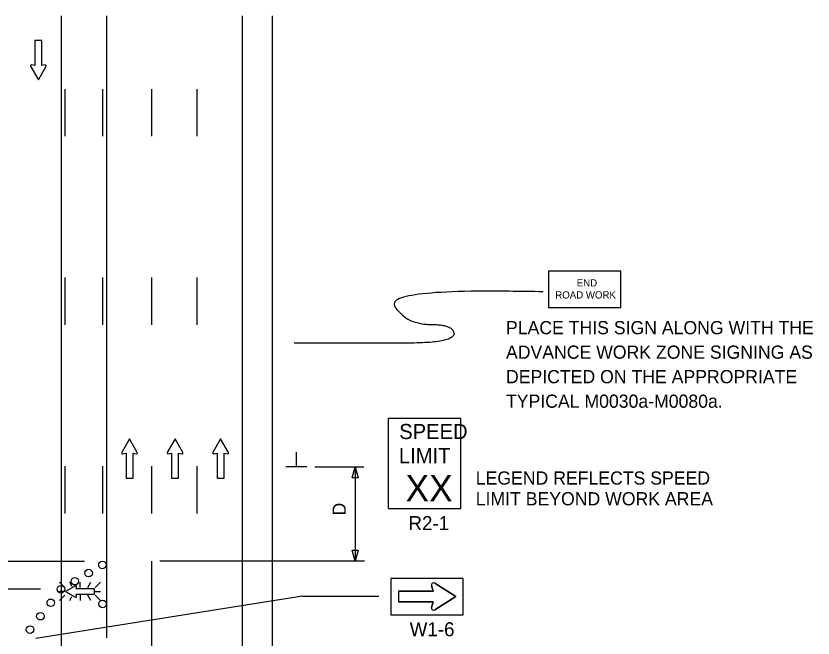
# Model space of a CAD drawing. Extents: x 16544 to 19504, y 5662 to 6909.
# Drawn here: x 16987.5 to 17410.3, y 6550.1 to 6880 of the extents above; entities that cross this region are included whole.
import ezdxf

# ---------------------------------------------------------------- set-up
doc = ezdxf.new("R2010")
doc.units = 0
for name, color, linetype in [('ALI_LEGAL_EX', 7, 'Continuous'), ('MT_SCRATCH_LEVEL_E', 7, 'Continuous'), ('PAVT_EDGE_EX', 7, 'Continuous'), ('TRAFFIC_SIGNS_PR', 7, 'Continuous'), ('TYPICAL_TEXT_DIMEN_PR', 7, 'Continuous')]:
    doc.layers.add(name, color=color, linetype=linetype)

msp = doc.modelspace()

# ---------------------------------------------------------------- linework, layer by layer
at = {"layer": 'ALI_LEGAL_EX'}
for points in [[(17013.46, 6841.23), (17013.46, 6816.23)], [(17033.46, 6841.23), (17033.46, 6816.23)], [(17059.46, 6841.23), (17059.46, 6816.23)], [(17083.46, 6841.23), (17083.46, 6816.23)], [(17013.46, 6741.23), (17013.46, 6716.23)], [(17013.46, 6741.23), (17013.46, 6716.23)], [(17033.46, 6741.23), (17033.46, 6716.23)], [(17033.46, 6741.23), (17033.46, 6716.23)], [(17059.46, 6741.23), (17059.46, 6716.23)], [(17059.46, 6741.23), (17059.46, 6716.23)], [(17083.46, 6741.23), (17083.46, 6716.23)], [(17013.46, 6641.23), (17013.46, 6616.23)], [(17013.46, 6641.23), (17013.46, 6616.23)], [(17033.46, 6641.23), (17033.46, 6616.23)], [(17033.46, 6641.23), (17033.46, 6616.23)], [(17059.46, 6641.23), (17059.46, 6616.23)], [(17059.46, 6641.23), (17059.46, 6616.23)], [(17083.46, 6641.23), (17083.46, 6616.23)]]:
    msp.add_lwpolyline(points, dxfattribs=at)
at = {"layer": 'MT_SCRATCH_LEVEL_E'}
for p, q in [((17001.2, 6866.95), (16997.46, 6866.95)), ((16997.46, 6866.95), (16997.46, 6853.69)), ((17001.2, 6866.95), (16997.46, 6866.95)), ((16997.46, 6866.95), (16997.46, 6853.69)), ((17001.2, 6853.69), (17001.2, 6866.95)), ((17001.2, 6853.69), (17001.2, 6866.95)), ((16995.2, 6853.32), (16999.35, 6846.09)), ((16995.2, 6853.32), (16999.35, 6846.09)), ((16997.46, 6853.69), (16995.68, 6854.01)), ((16997.46, 6853.69), (16995.68, 6854.01)), ((16999.35, 6846.09), (17003.46, 6853.32)), ((16999.35, 6846.09), (17003.46, 6853.32)), ((17002.98, 6854.01), (17001.2, 6853.69)), ((17002.98, 6854.01), (17001.2, 6853.69)), ((17047.7, 6655.73), (17043.59, 6648.49)), ((17047.7, 6655.73), (17043.59, 6648.49)), ((17051.85, 6648.49), (17047.7, 6655.73)), ((17051.85, 6648.49), (17047.7, 6655.73)), ((17071.87, 6655.73), (17067.76, 6648.49)), ((17071.87, 6655.73), (17067.76, 6648.49)), ((17076.02, 6648.49), (17071.87, 6655.73)), ((17076.02, 6648.49), (17071.87, 6655.73)), ((17096.04, 6655.73), (17091.93, 6648.49)), ((17096.04, 6655.73), (17091.93, 6648.49)), ((17100.19, 6648.49), (17096.04, 6655.73)), ((17100.19, 6648.49), (17096.04, 6655.73)), ((17044.07, 6647.81), (17045.85, 6648.12)), ((17044.07, 6647.81), (17045.85, 6648.12)), ((17045.85, 6648.12), (17045.85, 6634.86)), ((17045.85, 6648.12), (17045.85, 6634.86)), ((17049.59, 6634.86), (17049.59, 6648.12)), ((17049.59, 6648.12), (17051.37, 6647.81)), ((17049.59, 6634.86), (17049.59, 6648.12)), ((17049.59, 6648.12), (17051.37, 6647.81)), ((17068.24, 6647.81), (17070.02, 6648.12)), ((17068.24, 6647.81), (17070.02, 6648.12)), ((17070.02, 6648.12), (17070.02, 6634.86)), ((17070.02, 6648.12), (17070.02, 6634.86)), ((17073.76, 6634.86), (17073.76, 6648.12)), ((17073.76, 6648.12), (17075.54, 6647.81)), ((17073.76, 6634.86), (17073.76, 6648.12)), ((17073.76, 6648.12), (17075.54, 6647.81)), ((17092.41, 6647.81), (17094.19, 6648.12)), ((17092.41, 6647.81), (17094.19, 6648.12)), ((17094.19, 6648.12), (17094.19, 6634.86)), ((17094.19, 6648.12), (17094.19, 6634.86)), ((17097.93, 6634.86), (17097.93, 6648.12)), ((17097.93, 6648.12), (17099.71, 6647.81)), ((17097.93, 6634.86), (17097.93, 6648.12)), ((17097.93, 6648.12), (17099.71, 6647.81)), ((17045.85, 6634.86), (17049.59, 6634.86)), ((17045.85, 6634.86), (17049.59, 6634.86)), ((17070.02, 6634.86), (17073.76, 6634.86)), ((17070.02, 6634.86), (17073.76, 6634.86)), ((17094.19, 6634.86), (17097.93, 6634.86)), ((17094.19, 6634.86), (17097.93, 6634.86))]:
    msp.add_line(p, q, dxfattribs=at)
for centre, start, end in [((16995.61, 6853.55), 80.0362, 209.7731), ((16995.61, 6853.55), 80.0362, 209.7731), ((17003.05, 6853.55), 330.4248, 99.9638), ((17003.05, 6853.55), 330.4248, 99.9638), ((17044, 6648.26), 150.4248, 279.9638), ((17044, 6648.26), 150.4248, 279.9638), ((17051.44, 6648.27), 260.0362, 29.7731), ((17051.44, 6648.27), 260.0362, 29.7731), ((17068.17, 6648.26), 150.4248, 279.9638), ((17068.17, 6648.26), 150.4248, 279.9638), ((17075.61, 6648.27), 260.0362, 29.7731), ((17075.61, 6648.27), 260.0362, 29.7731), ((17092.34, 6648.26), 150.4248, 279.9638), ((17092.34, 6648.26), 150.4248, 279.9638), ((17099.78, 6648.27), 260.0362, 29.7731), ((17099.78, 6648.27), 260.0362, 29.7731)]:
    msp.add_arc(centre, 0.463, start, end, dxfattribs=at)
at = {"layer": 'PAVT_EDGE_EX'}
for p, q in [((17011.46, 6880.02), (17011.46, 6516.57)), ((17035.46, 6880.02), (17035.46, 6550.27)), ((17107.46, 6880.02), (17107.46, 6106.05)), ((17123.46, 6880.02), (17123.46, 6106.05)), ((17011.46, 6794.72), (17011.46, 6522.22)), ((17035.46, 6794.72), (17035.46, 6552.57)), ((17059.46, 6590.85), (17059.46, 6538.35))]:
    msp.add_line(p, q, dxfattribs=at)
at = {"layer": 'TRAFFIC_SIGNS_PR'}
for p, q in [((17185.03, 6666.76), (17223.43, 6666.76)), ((17185.03, 6618.76), (17185.03, 6666.76)), ((17223.43, 6618.76), (17223.43, 6666.76)), ((17185.03, 6618.76), (17223.43, 6618.76)), ((17010.54, 6579.66), (17013.36, 6576.84)), ((17017.26, 6577.48), (17016, 6579.66)), ((17021.45, 6576.84), (17021.45, 6579.66)), ((17025.58, 6576.84), (17027.21, 6579.66)), ((17029.53, 6576.84), (17032.35, 6579.66)), ((17208.8, 6574.87), (17207.96, 6577.93)), ((17209.64, 6579.18), (17220.8, 6572.07)), ((17013.36, 6574.81), (17010.54, 6574.81)), ((17010.54, 6569.96), (17013.36, 6572.78)), ((17015.98, 6569.96), (17017.19, 6572.05)), ((17021.45, 6572.78), (17021.45, 6569.96)), ((17027.24, 6569.96), (17025.61, 6572.78)), ((17029.53, 6574.81), (17032.35, 6574.81)), ((17029.53, 6572.78), (17032.35, 6569.96)), ((17190.4, 6574.87), (17208.8, 6574.87)), ((17190.4, 6574.87), (17190.4, 6569.27)), ((17220.8, 6572.07), (17209.64, 6564.97)), ((17208.8, 6569.27), (17190.4, 6569.27)), ((17207.96, 6566.21), (17208.8, 6569.27))]:
    msp.add_line(p, q, dxfattribs=at)
for points in [[(17269.97, 6725.41), (17308.37, 6725.41), (17308.37, 6744.61), (17269.97, 6744.61)], [(17186.4, 6562.47), (17224.8, 6562.47), (17224.8, 6581.67), (17186.4, 6581.67)]]:
    msp.add_lwpolyline(points, close=True, dxfattribs=at)
for points in [[(17019.12, 6577.82), (17013.81, 6574.81), (17019.12, 6571.77)], [(17019.62, 6572.13), (17019.39, 6573.42), (17029.11, 6573.42), (17029.11, 6576.17), (17019.39, 6576.17), (17019.62, 6577.47)], [(17207.96, 6577.93), (17208.8, 6574.87), (17190.4, 6574.87), (17190.4, 6569.27), (17208.8, 6569.27), (17207.96, 6566.21)], [(17209.64, 6564.97), (17220.8, 6572.07), (17209.64, 6579.18)]]:
    msp.add_lwpolyline(points, dxfattribs=at)
for centre in [(17033.35, 6588.85), (17033.35, 6588.85), (17026.02, 6584.54), (17018.69, 6580.23), (17011.36, 6575.93), (17005.94, 6568.79), (17033.4, 6568.18), (17000.45, 6561.67), (16994.95, 6554.54)]:
    msp.add_circle(centre, 2, dxfattribs=at)
for centre, radius, start, end in [((17019.28, 6577.53), 0.341, 350.7308, 118.8916), ((17209.04, 6578.23), 1.12, 57.5304, 195.3269), ((17209.04, 6578.23), 1.12, 57.5304, 195.3269), ((17019.28, 6572.07), 0.341, 241.4833, 9.9593), ((17209.04, 6565.92), 1.12, 164.6731, 302.4696), ((17209.04, 6565.92), 1.12, 164.6731, 302.4696)]:
    msp.add_arc(centre, radius, start, end, dxfattribs=at)
at = {"layer": 'TYPICAL_TEXT_DIMEN_PR'}
for p, q in [((17136.22, 6640.85), (17136.22, 6648.64)), ((17141.84, 6640.85), (17130.59, 6640.85)), ((17146.09, 6640.85), (17172.09, 6640.85)), ((17165.89, 6634.99), (17167.46, 6640.85)), ((17167.46, 6640.85), (17167.46, 6590.85)), ((17167.46, 6640.85), (17169.03, 6634.99)), ((17167.46, 6634.99), (17165.89, 6634.99)), ((17169.03, 6634.99), (17167.46, 6634.99)), ((17167.46, 6590.85), (17165.89, 6596.72)), ((17165.89, 6596.72), (17167.46, 6596.72)), ((17167.46, 6596.72), (17169.03, 6596.72)), ((17169.03, 6596.72), (17167.46, 6590.85)), ((16874.36, 6590.85), (17023.87, 6590.85)), ((17172.46, 6590.85), (17063.88, 6590.85)), ((17000.44, 6575.93), (16848.78, 6575.93)), ((17139.51, 6572.32), (16997.97, 6549.9)), ((17139.51, 6572.32), (17179.97, 6572.32))]:
    msp.add_line(p, q, dxfattribs=at)
msp.add_open_spline([(17267.18, 6733.73), (17182.47, 6735.74), (17194.58, 6716.43), (17219.76, 6716.43), (17219.76, 6706.52), (17170.11, 6706.52), (17135.05, 6706.52)], degree=2, dxfattribs=at)

# ---------------------------------------------------------------- texts
at = {"layer": 'TRAFFIC_SIGNS_PR'}
for s, height, p in [('END', 3.831, (17284.97, 6736.54)), ('ROAD WORK', 3.831, (17273.58, 6730.16)), ('PLACE THIS SIGN ALONG WITH THE', 7, (17247.43, 6711.22)), ('ADVANCE WORK ZONE SIGNING AS', 7, (17247.43, 6698.22)), ('DEPICTED ON THE APPROPRIATE', 7, (17247.43, 6685.22)), ('TYPICAL M0030a-M0080a.', 7, (17247.43, 6672.22)), ('SPEED', 8, (17190.8, 6655.62)), ('LIMIT', 8, (17190.63, 6642.82)), ('XX', 14.031, (17194.14, 6622.52)), ('LEGEND REFLECTS SPEED', 7, (17231.38, 6631.47)), ('LIMIT BEYOND WORK AREA', 7, (17231.38, 6620.47)), ('R2-1', 7.44, (17195.71, 6607.32)), ('W1-6', 7.44, (17196.34, 6551.03))]:
    msp.add_text(s, height=height, dxfattribs=at).set_placement(p)
at = {"layer": 'TYPICAL_TEXT_DIMEN_PR'}
msp.add_text('D', height=7, rotation=90, dxfattribs=at).set_placement((17162.46, 6615.07))

doc.saveas('drawing.dxf')
